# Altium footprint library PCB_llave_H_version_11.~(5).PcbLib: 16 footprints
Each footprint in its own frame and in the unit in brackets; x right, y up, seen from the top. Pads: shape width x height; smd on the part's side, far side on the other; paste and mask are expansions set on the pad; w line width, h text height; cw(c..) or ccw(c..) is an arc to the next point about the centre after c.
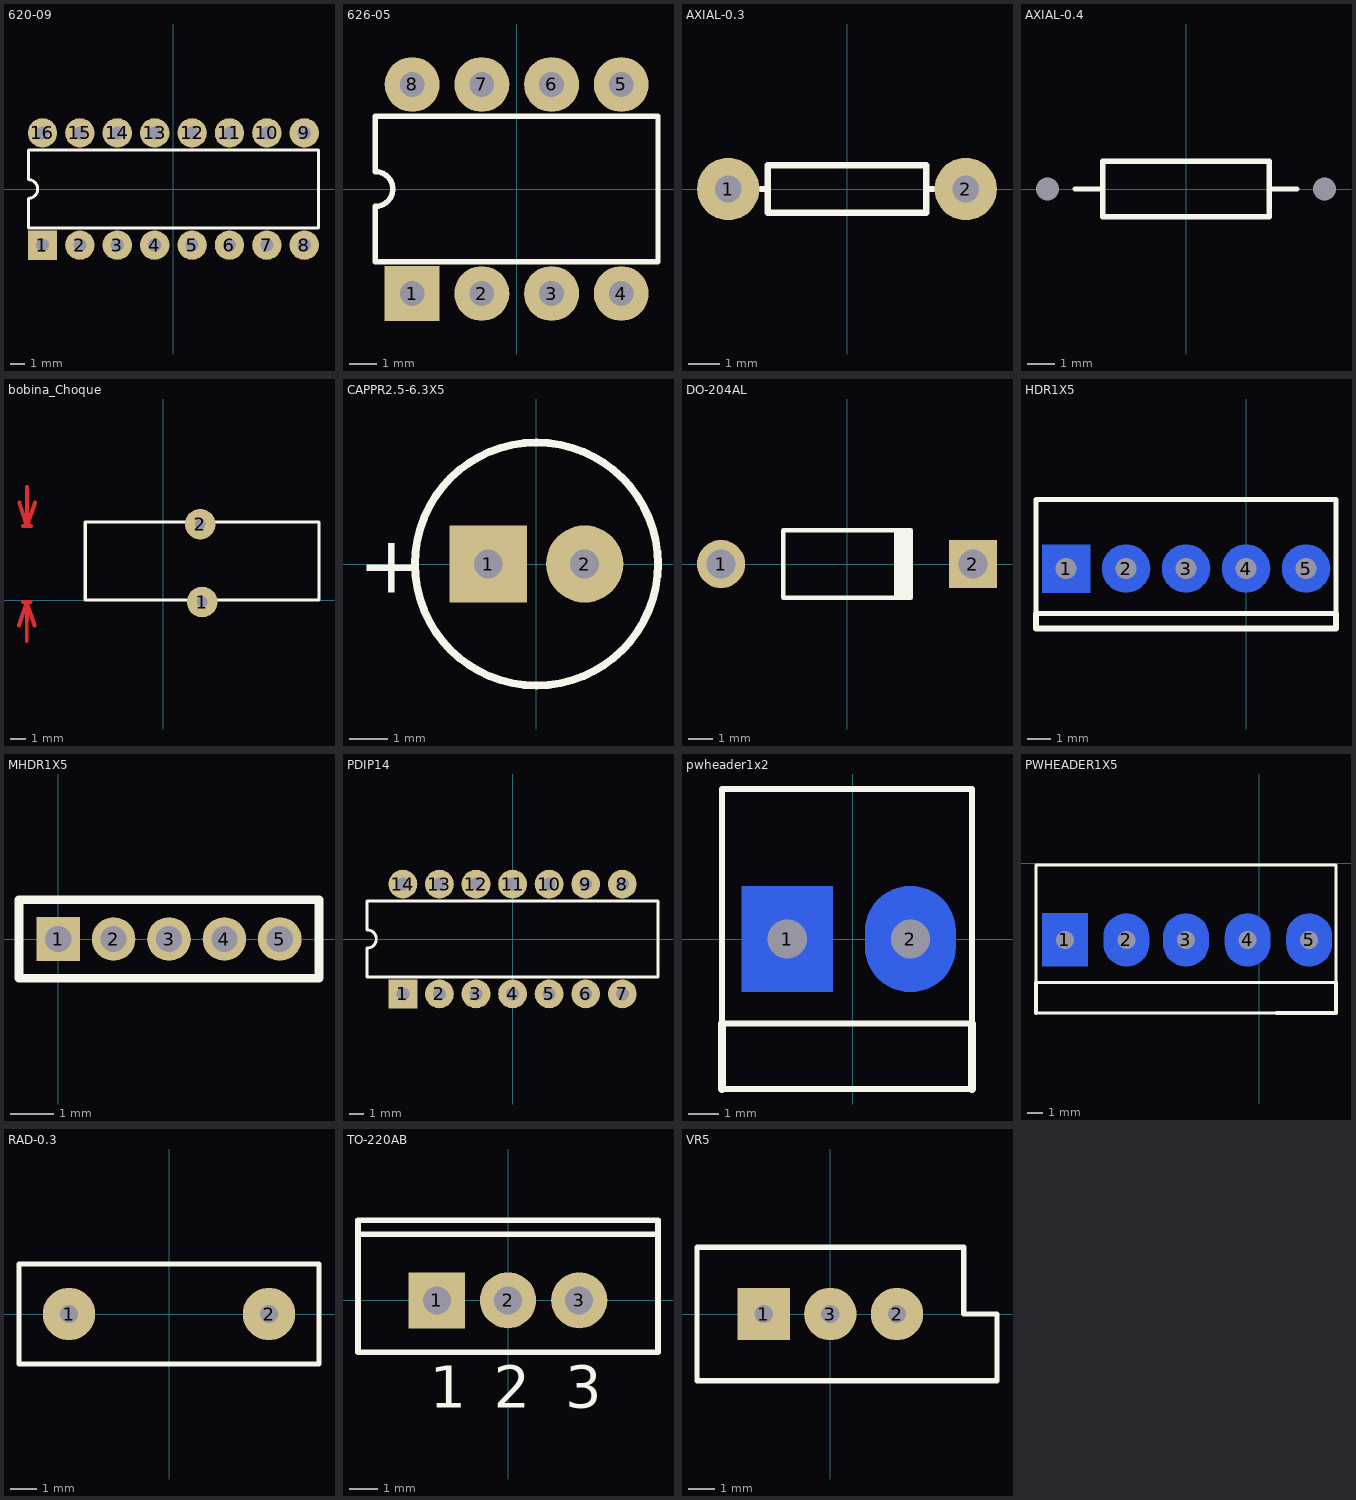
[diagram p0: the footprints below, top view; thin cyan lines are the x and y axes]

## 620-09 [mm] "DIP; 16 Leads; Row Spacing 7.62 mm; Pitch 2.54 mm"
height 4.19
pads (16):
  rect 2x2 hole 0.9: 1(-8.89,-3.81)
  round 2 hole 0.9: 2(-6.35,-3.81) 3(-3.81,-3.81) 4(-1.27,-3.81) 5(1.27,-3.81) 6(3.81,-3.81) 7(6.35,-3.81) 8(8.89,-3.81) 9(8.89,3.81) 10(6.35,3.81) 11(3.81,3.81) 12(1.27,3.81) 13(-1.27,3.81) 14(-3.81,3.81) 15(-6.35,3.81) 16(-8.89,3.81)
Top Overlay:
  lines w0.2: -9.85,-2.65 9.85,-2.65 9.85,2.65 -9.85,2.65 -9.85,0.635 cw(c-9.85,0) -9.85,-0.635 -9.85,-2.65

## 626-05 [mm] "DIP; 8 Leads; Row Spacing 7.62 mm; Pitch 2.54 mm"
height 4.45
pads (8):
  rect 2x2 hole 0.9: 1(-3.81,-3.81)
  round 2 hole 0.9: 2(-1.27,-3.81) 3(1.27,-3.81) 4(3.81,-3.81) 5(3.81,3.81) 6(1.27,3.81) 7(-1.27,3.81) 8(-3.81,3.81)
Top Overlay:
  lines w0.2: -5.15,-2.65 5.15,-2.65 5.15,2.65 -5.15,2.65 -5.15,0.635 cw(c-5.15,0) -5.15,-0.635 -5.15,-2.65

## AXIAL-0.3 [mm] "Resistor; 2 Leads"
height 1.524
pads (2):
  round 2 hole 0.85: 1(-3.81,0) 2(3.81,0)
Top Overlay:
  lines w0.2: -2.769,0 -2.54,0 ; 2.769,0 2.54,0 ; 2.54,0 2.54,-0.762 -2.54,-0.762 -2.54,0.762 2.54,0.762 2.54,0

## AXIAL-0.4 [mm] "Resistor; 2 Leads"
height 2.032
pads (2):
  round 0 / inner round 0 / far side round 2 hole 0.85: 1(-5.08,0) 2(5.08,0)
Top Overlay:
  lines w0.2: -4.064,0 -3.048,0 ; 3.048,0 4.064,0 ; -3.048,-1.016 3.048,-1.016 3.048,1.016 -3.048,1.016 -3.048,-1.016

## bobina_Choque [mm]
pads (2):
  round 2 hole 0.7: 1(2.54,-0.127) 2(2.413,4.953)
Top Layer:
  lines w0.254: -9.402,-1.649 -8.89,-0.126 ; -9.381,6.356 -8.877,4.831 ; -9.144,-0.126 -8.636,-0.127 ; -9.131,4.832 -8.623,4.83 ; -8.897,-2.666 -8.89,-0.126 ; -8.871,7.371 -8.877,4.831 ; -8.386,-1.652 -8.89,-0.126 ; -8.365,6.354 -8.877,4.831
  text "4.957 (mm)" at -5.245,-4.665 h1.52
Top Overlay:
  lines w0.2: -5.08,0 -5.08,5.08 10.16,5.08 10.16,0 -5.08,0

## CAPPR2.5-6.3X5 [mm] "Capacitor, Electrolytic, Radial; Body 6.3 x 5 mm (Dia.xH typ); Pin Spacing 2.5 mm (typ)"
height 6
pads (2):
  rect 2x2 hole 0.75: 1(-1.25,0)
  round 2 hole 0.75: 2(1.25,0)
Top Overlay:
  circle w0.2: c0,0 r3.15
  text "+" at -4.625,-0.75 h1.5

## DO-204AL [mm] "Diode, Axial; Body 5.2 x 2.7 mm (LxDia. max), Lead Dia. 0.86 mm (max)"
height 2.7
pads (2):
  round 2 hole 1.2: 1(-5.23,0)
  rect 2x2 hole 1.2: 2(5.23,0)
Top Overlay:
  rectangle: 1.95,-1.399 2.75,1.401
  lines w0.2: 2.65,-1.4 -2.65,-1.4 -2.65,1.4 2.65,1.4

## HDR1X5 [mil]
pads (5):
  rect 80x80 smd far side: 1(-300,300)
  round 80 smd far side: 2(-200,300) 3(-100,300) 4(0,300) 5(100,300)
Top Overlay:
  lines w7.87: -350,225 -350,415 150,415 150,225 -350,225
  lines w10: -350,225 -350,200 150,200 150,225

## MHDR1X5 [mm] "Connector; Header; 5 Position"
pads (5):
  rect 1x1 hole 0.6: 1(0,0)
  round 1 hole 0.6: 2(1.27,0) 3(2.54,0) 4(3.81,0) 5(5.08,0)
Top Overlay:
  lines w0.2: -0.9,-0.9 5.98,-0.9 5.98,0.9 -0.9,0.9 -0.9,-0.9

## PCBComponent_1 [mm]

## PDIP14 [mm] "DIP; 14 Leads; Row Spacing 7.62 mm; Pitch 2.54 mm"
height 5.33
pads (14):
  rect 2x2 hole 0.9: 1(-7.62,-3.81)
  round 2 hole 0.9: 2(-5.08,-3.81) 3(-2.54,-3.81) 4(0,-3.81) 5(2.54,-3.81) 6(5.08,-3.81) 7(7.62,-3.81) 8(7.62,3.81) 9(5.08,3.81) 10(2.54,3.81) 11(0,3.81) 12(-2.54,3.81) 13(-5.08,3.81) 14(-7.62,3.81)
Top Overlay:
  lines w0.2: -10.1,-2.65 10.1,-2.65 10.1,2.65 -10.1,2.65 -10.1,0.635 cw(c-10.1,0) -10.1,-0.635 -10.1,-2.65

## pwheader1x2 [mm]
pads (2):
  rect 3x3.5 smd far side: 1(-2.159,0)
  oval 3x3.5 smd far side: 2(1.905,0)
Top Overlay:
  lines w0.2: -4.318,-4.953 3.937,-4.953 ; -4.318,-2.794 3.937,-2.794 3.937,4.953 -4.318,4.953 -4.318,-2.794
  lines w0.254: -4.318,-4.953 -4.318,-2.794 ; 3.937,-4.953 3.937,-2.794

## PWHEADER1X5 [mm]
pads (5):
  rect 3x3.5 smd far side: 1(-12.827,-5.08)
  oval 3x3.5 smd far side: 2(-8.763,-5.08) 3(-4.826,-5.08) 4(-0.762,-5.08) 5(3.302,-5.08)
Top Overlay:
  lines w0.2: -14.732,-9.906 1.143,-9.906 ; -14.732,-7.874 -5.842,-7.874 5.08,-7.874 5.08,-0.127 -14.732,-0.127 -14.732,-7.874
  lines w0.254: -14.732,-9.906 -14.732,-7.874 ; 1.143,-9.906 5.08,-9.906 5.08,-7.874

## RAD-0.3 [mm] "Capacitor; 2 Leads"
height 6
pads (2):
  round 2 hole 0.7: 1(-3.81,0) 2(3.81,0)
Top Overlay:
  lines w0.2: -5.715,-1.905 -5.715,1.905 5.715,1.905 5.715,-1.905 -5.715,-1.905

## TO-220AB [mm] "TO, Thru-Hole, Vertical, Heatsink Mounted; 3 In-Line Leads; Pitch 2.54 mm"
height 19.3
pads (3):
  rect 2x2 hole 1: 1(-2.54,0)
  round 2 hole 1: 2(0,0) 3(2.54,0)
Top Overlay:
  lines w0.2: -5.35,2.35 5.35,2.35 ; -5.35,-1.85 -5.35,2.85 5.35,2.85 5.35,-1.85 -5.35,-1.85
  text "3" at 2.04,-3.825 h1.5
  text "1" at -2.79,-3.825 h1.5
  text "2" at -0.5,-3.825 h1.5

## VR5 [mm] "Potentiometer; 3 Leads"
pads (3):
  rect 2x2 hole 0.7: 1(-2.54,0)
  round 2 hole 0.7: 2(2.54,0) 3(0,0)
Top Overlay:
  lines w0.2: -5.08,-2.54 -5.08,2.54 5.08,2.54 5.08,0 6.35,0 6.35,-2.54 -5.08,-2.54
